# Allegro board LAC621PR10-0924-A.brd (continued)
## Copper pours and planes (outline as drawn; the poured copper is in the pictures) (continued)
INT_SPKR_L+ on BOTTOM (solid shape): 284.54,17.61 284.54,15.65 284.44,15.55 283.37,15.55 283.22,15.7 283.22,17.63 283.32,17.73 284.42,17.73
INT_SPKR_L- on BOTTOM (solid shape): 284.47,7.78 284.47,5.49 284.14,5.16 283.6,5.16 283.42,5.34 283.42,7.78 283.5,7.85 284.39,7.85
INT_SPKR_L- on BOTTOM (solid shape): 286.24,17.63 286.24,15.68 286.14,15.57 285.08,15.57 284.92,15.73 284.92,17.66 285.03,17.76 286.12,17.76
INT_SPKR_R+ on BOTTOM (solid shape): 288.02,17.61 288.02,15.65 287.92,15.55 286.85,15.55 286.7,15.7 286.7,17.63 286.8,17.73 287.9,17.73
INT_SPKR_R+ on BOTTOM (solid shape): 285.96,7.67 285.96,7.47 285.69,7.19 285.69,5.36 285.48,5.16 284.85,5.16 284.69,5.31 284.69,7.8 285.05,8.16 285.48,8.16
INT_SPKR_R- on BOTTOM (solid shape): 289.72,17.61 289.72,15.65 289.62,15.55 288.56,15.55 288.4,15.7 288.4,17.63 288.5,17.73 289.6,17.73
INT_SPKR_R- on BOTTOM (solid shape): 288.24,7.31 288.24,7.18 286.93,5.87 286.93,5.39 286.68,5.13 286.19,5.13 286.02,5.31 286.02,6.79 287.13,7.9 287.64,7.9
LX_1.8VALW on BOTTOM (solid shape): 214.5,109.7 215.3,109.7 215.59,109.41 215.59,107.48 215.09,106.99 210.98,106.99 210.68,107.29 210.68,108.26 210.78,108.36 212.84,108.36 213.17,108.69 213.17,109.48 213.4,109.71 214.49,109.71
LX_1V_PRIM on BOTTOM (solid shape): 201.87,69.45 201.87,68.25 202.14,67.97 203.64,67.97 204.41,67.21 204.94,67.21 205.07,67.09 205.07,66.37 204.96,66.27 201.18,66.27 201.08,66.37 201.08,69.47 201.15,69.55 201.76,69.55
LX_1VS_VCCIO on BOTTOM (solid shape): 202.45,53.45 202.45,52.73 202.35,52.63 201.26,52.63 201.13,52.51 201.13,51.08 200.95,50.91 199.44,50.91 198.84,50.31 198.37,50.31 198.23,50.45 198.23,53.14 198.63,53.55 202.35,53.55
LX_3V on TOP (solid shape): 219.67,73.36 219.67,72.75 219.54,72.62 219.26,72.62 218.71,72.06 217,72.06 216.75,71.81 216.75,71.45 216.6,71.3 215.02,71.3 214.92,71.4 214.92,73.26 215.1,73.44 219.59,73.44
LX_3V on BOTTOM (solid shape): 215.28,75 215.28,73.21 215.58,72.9 219.59,72.9 220.1,72.39 220.1,71.76 220.03,71.68 218.17,71.68 218.05,71.56 218.05,67.75 217.72,67.42 213.68,67.42 213.57,67.52 213.57,75.37 213.81,75.61 214.67,75.61
LX_5V on TOP (solid shape): 221.14,63.83 221.14,63.17 221.04,63.07 220.33,63.07 220.28,63.02 220.28,62.74 220.1,62.56 218.35,62.56 218.07,62.28 218.07,61.65 218.02,61.6 216.37,61.6 216.32,61.65 216.32,63.76 216.45,63.88 221.09,63.88
LX_5V on BOTTOM (solid shape): 219.56,63.95 221.49,63.95 221.63,63.81 221.63,63.28 221.86,63.05 221.86,62.49 221.75,62.39 220.34,62.39 218.99,61.04 218.99,58.8 218.83,58.65 216.55,58.65 216.47,58.73 216.47,63.61 216.83,63.96 219.54,63.96
NB_PSID on BOTTOM (solid shape): 53.79,94.02 53.79,94.01 53.85,93.92 53.93,93.85 53.94,93.83 53.95,93.8 53.95,93.14 52.73,91.93 45.7,91.93 45.63,91.99 45.63,92.74 45.67,92.78 52.17,92.78 53.48,94.09 53.71,94.09
PBAT_PRES#_C on BOTTOM (solid shape): 59.74,21.1 60.6,19.6 60.51,19.27 60.21,19.1 59.88,19.18 59.02,20.68 59.11,21.01 59.41,21.19
PBAT_SMBCLK_C on BOTTOM (solid shape): 62.33,22.6 63.19,21.1 63.11,20.77 62.8,20.6 62.48,20.68 61.62,22.18 61.71,22.51 62.01,22.69
PBAT_SMBDAT_C on BOTTOM (solid shape): 61.03,21.85 61.9,20.35 61.81,20.02 61.5,19.85 61.18,19.93 60.32,21.43 60.41,21.76 60.71,21.94
PBATT+_C on TOP (solid shape): 62.47,22.97 62.47,22.2 62.7,21.97 68.77,21.97 69.48,21.26 69.48,18.58 69.23,18.33 63.16,18.33 62.81,18.68 62.81,20.68 62.66,20.83 61.89,20.83 61.55,21.17 61.55,22.76 61.9,23.11 62.33,23.11
PBATT+_C on BOTTOM (solid shape): 66.18,25.35 66.2,25.35 66.22,25.33 67.8,23.09 68.11,22.79 68.11,18.73 67.73,18.35 64.07,18.35 63.98,18.45 63.97,18.46 63.97,18.48 63.97,19.52 63.5,19.99 63.5,21.81 63.38,21.93 62.76,22.84 62.76,23.33 64.79,25.35
RING2 on TOP (solid shape): 289.37,33.76 289.37,32.13 289.27,32.03 287.84,32.03 287.64,32.24 287.64,33.67 287.76,33.78 288.02,33.78 288.02,33.79 289.34,33.79
RING2 on TOP (solid shape): 283.91,32.44 283.91,32.41 283.93,32.39 283.93,32.34 284.11,32.16 284.11,32.01 283.97,31.87 283.79,31.87 283.52,32.14 283.51,32.14 283.38,32.26 283.2,32.26 283.09,32.38 281.76,32.38 281.7,32.44 281.7,32.57 281.72,32.59 283.76,32.59
RING2 on IN1 (solid shape): 288.78,33.02 288.78,31.78 288.25,31.25 283.98,31.25 283.12,32.11 283.12,32.44 283.25,32.57 286.73,32.57 287.49,33.33 288.48,33.33
RING2_R on TOP (solid shape): 295.06,34.36 295.06,31.83 294.85,31.63 293.92,31.63 293.56,31.98 293.56,33.53 293.43,33.66 293.36,33.66 293.25,33.56 293.25,32.31 292.98,32.03 289.75,32.03 289.62,32.16 289.62,32.85 289.72,32.95 291.68,32.95 291.98,33.25 291.98,34.07 292.47,34.55 294.87,34.55
RING2_R on IN2 (solid shape): 294.88,31.96 294.88,30.1 294.7,29.93 293.79,29.93 293.56,30.15 293.56,31.98 293.69,32.11 294.73,32.11
RING2_R on IN2 (solid shape): 301.48,19.43 301.79,19.43 302.17,19.05 302.17,18.6 301.93,18.36 300.47,18.36 299.78,19.05 299.78,19.26 299.6,19.43 299.38,19.43 299.22,19.59 299.22,20.76 299.27,20.81 300.11,20.81
SA_LGATE on BOTTOM (solid shape): 100.08,84.35 100.09,84.33 100.09,84.32 100.12,84.14 100.23,83.99 100.24,83.97 100.24,83.95 100.24,82.9 100.13,82.78 99.81,82.78 99.79,82.77 99.3,82.77 99.2,82.87 99.2,83.12 99.63,83.56 99.64,83.68 99.64,84.27 99.76,84.39 100.04,84.39
SA_LGATE on IN2 (solid shape): 100.09,84.22 100.1,84.2 100.13,84.1 100.2,84.01 100.21,83.99 100.22,83.97 100.22,83.82 100.52,83.52 100.52,82.81 100.44,82.73 99.44,82.73 99.07,83.1 99.07,84.19 99.2,84.32 99.99,84.32
SA_LGATE on IN2 (solid shape): 107.68,83.39 107.68,82.86 107.54,82.72 107.42,82.72 107.4,82.71 105.4,82.71 105.27,82.83 105.27,83.33 105.31,83.4 105.39,83.43 105.57,83.43 105.72,83.51 105.73,83.52 107.56,83.52
SA_SNUB on TOP (solid shape): 113.11,83.88 113.11,83.16 112.75,82.8 109.32,82.8 109.14,82.97 109.14,83.89 109.24,83.99 113,83.99
SA_SW on TOP (solid shape): 111.79,82.18 112.93,82.18 113.17,81.94 113.17,80.62 112.74,80.19 108.34,80.19 107.85,80.68 107.75,80.87 107.56,80.97 107.33,81.21 107.33,82.1 107.43,82.2 111.77,82.2
SA_SW on BOTTOM (solid shape): 110.43,83.9 110.43,80.83 110.15,80.55 108.19,80.55 107.68,81.06 107.33,81.06 106.69,81.69 102.53,81.69 102.07,82.15 102.07,82.3 101.7,82.67 101.7,82.69 101.68,82.69 101.56,82.81 101.43,82.81 101.38,82.86 101.38,83.49 101.5,83.6 102.03,83.6 102.19,83.45 102.2,83.45 102.27,83.38 103.02,83.38 103.62,82.78 107.61,82.78 107.89,83.07 107.89,83.71 108.22,84.03 110.29,84.03
SA_UGATE on BOTTOM (solid shape): 107.78,80.78 107.78,80.24 107.15,79.61 106.03,79.61 105.93,79.71 105.93,80.6 106.03,80.7 106.62,80.7 106.84,80.93 107.63,80.93
SA_UGATE on IN2 (solid shape): 103.08,81.41 103.08,80.47 102.98,80.37 101.48,80.37 101.33,80.52 101.33,81.41 101.41,81.49 103.01,81.49
SA_UGATE on IN2 (solid shape): 107.96,80.67 107.96,80.01 107.71,79.76 106.03,79.76 105.55,80.24 105.55,80.34 106.03,80.83 107.81,80.83
SLEEVE on TOP (solid shape): 290.77,41.13 290.77,40.91 289.88,40.03 289.88,39.79 289.59,39.5 289.29,39.5 289.17,39.63 289.17,41.02 289.44,41.3 290.59,41.3
SLEEVE on TOP (solid shape): 289.42,35.79 289.42,34.14 289.37,34.09 288.04,34.09 287.93,34.2 287.93,35.78 287.98,35.83 288.31,35.83 288.34,35.86 289.35,35.86
SLEEVE on TOP (solid shape): 283.91,33.13 283.91,32.77 283.86,32.72 283.49,32.72 283.35,32.75 283.21,32.72 281.7,32.72 281.7,32.97 281.72,33 282.91,33 283.08,33.17 283.16,33.15 283.25,33.15 283.32,33.15 283.39,33.16 283.49,33.2 283.83,33.2
SLEEVE on IN1 (solid shape): 290.56,40.49 290.56,38.87 290.41,38.71 290.26,38.71 289.57,38.03 289.55,38.03 289.25,37.92 289.14,37.62 289.14,37.6 288.91,37.37 288.91,34.27 288.4,33.76 286.5,33.76 285.51,32.77 282.94,32.77 282.84,32.87 282.84,33.07 282.97,33.2 283.11,33.2 283.12,33.2 283.3,33.15 283.49,33.2 283.68,33.2 285.23,34.75 286.98,34.75 287.31,35.08 287.31,37.89 287.34,37.91 287.46,38 287.54,38.13 287.55,38.14 288.02,38.61 288.04,38.61 288.27,38.72 288.38,38.95 288.38,38.97 289.06,39.65 289.06,40.54 289.24,40.72 290.33,40.72
SLEEVE_R on TOP (solid shape): 294.99,36.07 294.99,34.85 294.9,34.76 294.74,34.76 294.73,34.75 291.78,34.75 291.68,34.65 291.2,34.65 290.87,34.98 289.72,34.98 289.6,35.11 289.6,36.22 289.7,36.33 294.73,36.33
SLEEVE_R on TOP (solid shape): 295.13,30.96 295.13,29.66 293.08,27.62 292.23,27.62 291.97,27.36 291.97,25.99 292.91,25.05 292.91,24.36 292.97,24.3 292.97,21.16 293.41,20.73 297.93,20.73 299,19.66 299.5,19.66 299.79,19.37 299.79,18.47 299.65,18.34 298.26,18.34 296.94,19.65 291.81,19.65 291.5,19.96 291.5,24.02 290.51,25.02 290.51,28.78 291.27,29.54 292.98,29.54 293.37,29.94 293.37,30.33 293.28,30.42 292.62,30.42 292.44,30.6 292.44,31.38 292.5,31.44 292.51,31.44 292.52,31.45 294.64,31.45
SLEEVE_R on IN1 (solid shape): 294.83,35.03 294.83,34.34 294.33,33.84 294.33,33.83 293.36,32.86 293.36,30.74 293.03,30.41 292.24,30.41 292.01,30.64 292.01,33.55 293.12,34.66 293.14,34.66 293.74,35.26 294.6,35.26
SNB_+1VALWP on BOTTOM (solid shape): 221.93,56.14 221.93,55.12 221.93,55.12 221.93,54.16 221.86,54.09 219.95,54.09 219.77,54.27 219.77,56.16 219.78,56.17 219.78,56.39 219.86,56.47 221.6,56.47
SNUB_1.2V on BOTTOM (solid shape): 81.9,51.01 82.76,51.01 82.82,50.96 82.82,48.85 82.45,48.48 80.98,48.48 80.98,48.49 80.75,48.49 80.6,48.64 80.6,49.53 80.61,49.53 80.61,51.18 80.68,51.26 81.65,51.26
SNUB_1.8VALW on BOTTOM (solid shape): 212.84,110.33 212.84,108.67 212.69,108.51 210.98,108.51 210.86,108.64 210.86,109.48 210.97,109.59 210.97,110.28 211.12,110.43 212.74,110.43
SNUB_1V_PRIM on BOTTOM (solid shape): 205.09,69.32 205.09,67.82 204.99,67.72 204.15,67.72 203.92,67.95 203.92,69.27 204,69.35 205.07,69.35
SNUB_1VS_VCCIO on BOTTOM (solid shape): 200.09,50.27 200.28,50.22 200.47,50.27 201.05,50.27 201.1,50.22 201.1,49.54 200.98,49.42 200.6,49.42 200.49,49.43 200.39,49.42 199.44,49.42 199.27,49.58 199.27,50.19 199.35,50.27
SW_1.2V on BOTTOM (solid shape): 80.73,56.29 86.3,56.29 86.45,56.14 86.45,53.72 86.35,53.62 81.67,53.62 80.33,52.28 80.33,50.37 79.31,49.36 78.09,49.36 77.76,49.69 77.76,56.7 77.91,56.85 80.17,56.85
SW_1.2V on BOTTOM (solid shape): 91.38,53.57 91.38,53.34 91.36,53.33 91.36,53.18 90.84,52.66 90.54,52.66 90.36,52.48 88.53,52.48 88.4,52.61 88.4,53.5 88.45,53.55 89.06,53.55 89.14,53.47 90.29,53.47 90.38,53.47 90.54,53.62 91.32,53.62
SW_1.2V on IN1 (solid shape): 90.38,53.34 90.38,52.52 90.26,52.39 88.24,52.39 88.15,52.48 88.15,53.29 88.3,53.45 90.28,53.45
SW_1.2V on IN1 (solid shape): 81.41,55.6 81.41,55.25 81.51,55.15 82.27,55.15 82.35,55.07 82.35,54.23 82.17,54.06 80.8,54.06 80.64,54.21 80.64,55.55 80.77,55.68 81.33,55.68
SW_+1VALWP on TOP (solid shape): 224.37,54.06 224.37,52.77 224.35,52.75 224.35,52.24 224.17,52.06 222.22,52.06 221.93,52.35 221.93,53.8 222.23,54.11 224.32,54.11
SW_+1VALWP on BOTTOM (solid shape): 219.52,56.37 219.52,54.16 219.92,53.75 223.84,53.75 223.91,53.67 223.91,52.58 223.84,52.51 222.13,52.51 221.6,51.97 221.6,50.35 221.04,49.79 218.2,49.79 217.74,50.25 217.74,53.62 217.05,54.31 217.05,56.49 217.27,56.7 219.18,56.7
N15438178 on TOP (solid shape): 57.85,85.25 57.85,83.06 57.8,82.99 57.78,82.9 57.77,82.86 55.92,82.86 55.64,83.14 55.64,85.22 55.71,85.3 57.8,85.3
N15438178 on BOTTOM (solid shape): 56.6,85.75 56.6,84.23 57.03,83.8 57.7,83.8 57.8,83.7 57.8,83.02 57.77,82.99 57.77,82.78 57.72,82.73 56.3,82.73 55.79,83.24 55.79,83.62 55.26,84.15 54.37,84.15 54.19,84.33 54.19,86.01 54.29,86.11 56.25,86.11
N15443707 on BOTTOM (solid shape): 61.84,86.87 61.84,86.01 61.94,85.91 61.94,85.19 62.55,84.58 62.55,83.8 61.56,83.8 61.48,83.87 61.48,84.74 61.61,84.86 61.61,84.9 61.61,84.91 61.66,85.09 61.61,85.27 61.61,85.29 61.61,85.49 61.61,85.5 61.66,85.68 61.61,85.86 61.61,85.87 61.61,85.98 61.56,86.04 61.56,86.9 61.61,86.95 61.76,86.95
N17156948 on TOP (solid shape): 44.39,87.35 44.39,86.08 44.13,85.83 42.94,85.83 42.81,85.96 42.81,87.3 42.96,87.46 44.28,87.46
N19817114 on TOP (solid shape): 77.43,25.57 78.61,25.57 79.43,24.75 79.43,21.24 77.87,19.69 75.4,19.69 75.18,19.9 75.18,20.77 75.04,20.91 74.64,20.91 74.31,20.91 74.02,21.19 74.02,25.08 74.52,25.58 77.43,25.58
N19957038 on TOP (solid shape): 78.16,27.28 78.16,25.75 78.12,25.7 74.7,25.7 74.31,26.09 74.3,26.1 74.3,26.12 74.3,26.86 74.77,27.33 78.11,27.33
N32114561 on BOTTOM (solid shape): 62.57,83.11 62.57,82.4 62.52,82.35 60.39,82.35 60.34,82.4 60.34,83.14 60.36,83.16 62.52,83.16
N39307859 on BOTTOM (solid shape): 87.79,54.77 87.79,52.68 87.72,52.61 86.96,52.61 86.85,52.71 86.85,54.74 86.96,54.84 87.72,54.84
N39352217 on BOTTOM (solid shape): 220.08,71 220.08,70.34 219.92,70.18 219.92,67.9 219.87,67.85 218.96,67.85 218.86,67.95 218.86,69.68 219.16,69.98 219.16,71.02 219.21,71.07 220,71.07
N39352229 on BOTTOM (solid shape): 217.23,75.18 217.23,74.43 217.28,74.38 217.28,73.44 217.21,73.36 215.58,73.36 215.56,73.38 215.56,75.35 215.76,75.56 216.86,75.56
N39352417 on BOTTOM (solid shape): 221.83,61.73 221.83,61.07 221.55,60.79 221.55,60.53 220.81,59.8 220.81,58.58 220.69,58.45 219.92,58.45 219.75,58.63 219.75,59.97 220.89,61.12 220.89,61.68 220.99,61.78 221.78,61.78
N39352440 on BOTTOM (solid shape): 220.59,65.61 220.59,64.72 220.36,64.49 218.81,64.49 218.58,64.72 218.58,65.51 218.76,65.69 220.51,65.69
N39431059 on BOTTOM (solid shape): 92.37,68.46 92.37,66.27 92.34,66.25 91.68,66.25 91.58,66.35 91.58,68.46 91.63,68.51 92.32,68.51
N39431065 on BOTTOM (solid shape): 94.17,67.03 96.02,67.03 96.1,66.96 96.1,66.83 96.05,66.78 94.91,66.78 94.35,66.22 92.94,66.22 92.73,66.44 92.73,67.1 92.82,67.19 94.02,67.19
N39431067 on BOTTOM (solid shape): 94.71,68.62 94.71,67.97 95.12,67.56 95.14,67.53 95.17,67.51 95.24,67.44 96.02,67.44 96.1,67.36 96.1,67.21 96.05,67.16 94.27,67.16 93.97,67.47 93.04,67.47 92.93,67.58 92.93,68.6 93.03,68.7 94.63,68.7
N39431132 on BOTTOM (solid shape): 86.8,77.63 86.8,75.54 86.68,75.42 86.02,75.42 85.97,75.47 85.97,77.63 86.04,77.7 86.73,77.7
N39431138 on BOTTOM (solid shape): 88.25,76.2 89.78,76.2 89.85,76.13 89.85,75.92 88.86,75.92 88.85,75.92 88.82,75.92 88.32,75.42 87.39,75.42 87.39,76.31 87.46,76.38 88.07,76.38
N39431140 on BOTTOM (solid shape): 88.28,77.65 88.28,77.09 88.76,76.61 89.78,76.61 89.85,76.53 89.85,76.36 89.83,76.33 88.53,76.33 88.52,76.34 88.34,76.34 88.02,76.66 87.46,76.66 87.39,76.74 87.39,77.68 87.44,77.73 88.2,77.73
N39435438 on BOTTOM (solid shape): 101.21,81.36 101.21,80.39 101.43,80.17 101.81,80.17 101.89,80.09 101.89,79.07 101.79,78.97 101.21,78.97 100.88,79.3 100.88,81.36 100.93,81.41 101.15,81.41
N39435440 on BOTTOM (solid shape): 103.39,81.06 103.39,79.12 103.26,79 102.6,79 102.48,79.12 102.48,80.27 102.37,80.37 102.37,80.51 102.38,80.52 102.41,80.67 102.38,80.83 102.37,80.84 102.37,81.09 102.39,81.13 103.31,81.13
N49522780 on TOP (solid shape): 39.97,82.43 39.97,81.72 40.14,81.54 41.28,81.54 41.47,81.35 41.47,80.86 41.23,80.62 39.13,80.62 39.03,80.73 39.03,81.79 39.25,82.02 39.25,82.48 39.31,82.53 39.86,82.53

Small or netless copper shapes (teardrops, artwork), in the pictures only: 175 on TOP, 66 on BOTTOM, 79 on IN2, 30 on IN3

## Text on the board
Ref Des/Silkscreen Bottom: H23 | H8 | H7 | PWB:6N3K7 | COPYRIGHT 2015 | REV:A00 | ALL RIGHT RESERVED
User.Comments: LA-C621P | 2016-09-24 | 2015-09-24 | ADM60 | Win | 275.67 | 223.15 | 209.00 | 56.09 | 19.37 | 0.41 | 8.41 | 13.50 | 101.80 | 61.24 | 3.44 | 0.00 | 28.40 | 95.72 | 35.55 | 39.75 | 21.20 | 51.63 | 95.48 | 81.10 | 81.00 | 66.95 | 19.31 | 14.60 | 239.73 | 225.27 | 193.85 | 156.60 | 0.54 | 57.21 | 16.78 | 0.43 | 83.30 | 94.42 | 37.15 | 98.42 | 3.35 | 211.49 | 86.30 | 76.45 | 44.30 | 31.15 | 12.45 | 2.40 | 225.25 | 212.23 | 130.23 | 47.40 | 24.55 | 20.60 | 16.81 | 8.40 | 80.73 | 72.20 | 35.71 | 12.20 | 9.48 | 3.86 | 0.65 | PCB CONNECTOR_TOP | PCB LIMIT_TOP | PCB LIMIT_BTM | PCB CONNECTOR_BTM
USER_PART_NUM_BOTTOM: 275.67 | 223.15 | 209.00 | 56.09 | 19.67 | 0.41 | 8.41 | 13.50 | 101.80 | 61.24 | 3.44 | 0.00 | 28.40 | 95.72 | 34.95 | 39.75 | 20.60 | 51.63 | 83.30 | 94.42 | 37.15 | 98.35 | 3.35 | 211.49 | 86.30 | 76.45 | 44.30 | 31.15 | 12.45 | 2.40
DEVICE_TYPE_BOTTOM: 95.48 | 81.10 | 81.00 | 66.95 | 19.31 | 14.60 | 239.73 | 225.27 | 193.85 | 156.60 | 0.54 | 57.21 | 16.58 | 0.53 | 225.25 | 212.23 | 130.23 | 61.30 | 47.40 | 24.55 | 20.60 | 16.81 | 8.40 | 0.00 | 80.73 | 72.20 | 35.71 | 12.20 | 9.48 | 3.86 | 0.65 | 57.01
DEVICE_TYPE_TOP: {\Fgdt;n}\Fcgomg.ttf;6.50 | {\Fgdt;n}\Fcgomg.ttf;8.00 | {\Fgdt;n}\Fcgomg.ttf;3.80 | {\Fgdt;n}\Fcgomg.ttf;2.40 | 281.10 | 3.00 | 2.00 | 238.85 | 187.10 | {\Fgdt;n}\Ftxt;3.30 | 170.85 | 104.85 | 67.85 | 38.15 | 37.35 | 11.68 | 5.85 | 103.60 | 80.35 | 49.00 | 48.50 | 6.50 | 0.00 | 43.00 | 62.95 | 101.00 | 92.50 | 83.05 | 74.15 | 46.85 | 14.00 | 6.70 | 6.05 | 245.60 | 168.20 | 137.85 | 107.50 | 59.85 | 52.75 | {\Fgdt;n}\Ftxt;3.20 | 4.15
PAGE_OUTLINE: 101.40 | 101.00 | 92.50 | 83.05 | 74.15 | 46.85 | 6.70 | {\Fgdt;n}\Ftxt;2.40 | {\Fgdt;n}\Ftxt;6.50 | 238.85 | {\Fgdt;n}\Ftxt;3.30 | 187.10 | {\Fgdt;n}\Ftxt;8.00 | {\Fgdt;n}\Ftxt;5.50 | {\Fgdt;n}\Ftxt;3.80 | 170.85 | 153.85 | 104.85 | 67.85 | {\Fgdt;n}\Ftxt;3.20 | 37.35 | 11.68 | 5.85 | 281.10 | 245.60 | 168.20 | 137.85 | 107.50 | 59.85 | 52.75 | 38.15 | 0.00 | 4.15 | 103.60 | 100.00 | 80.35 | 62.95 | 49.00 | 48.50 | 43.00 | 6.50 | 2.00
User.11: 107.75 | 0.00 | 5.35 | 291.10 | 15.20
User.12: 275.67 | 223.15 | 209.00 | 56.09 | 19.67 | 0.41 | 8.41 | 13.50 | 101.80 | 61.24 | 3.44 | 0.00 | 28.40 | 95.72 | 34.95 | 39.75 | 20.60 | 51.63 | 83.30 | 94.42 | 37.15 | 98.35 | 3.35 | 211.49 | 86.30 | 76.45 | 44.30 | 31.15 | 12.45 | 2.40
User.13: 95.48 | 81.10 | 81.00 | 66.95 | 19.31 | 14.60 | 239.73 | 225.27 | 193.85 | 156.60 | 0.54 | 57.21 | 16.58 | 0.53 | 225.25 | 212.23 | 130.23 | 61.30 | 47.40 | 24.55 | 20.60 | 16.81 | 8.40 | 0.00 | 80.73 | 72.20 | 35.71 | 12.20 | 9.48 | 3.86 | 0.65 | 57.01
User.16: {\Fgdt;n}\Fcgomg.ttf;6.50 | {\Fgdt;n}\Fcgomg.ttf;8.00 | {\Fgdt;n}\Fcgomg.ttf;3.80 | {\Fgdt;n}\Fcgomg.ttf;2.40 | 281.10 | 3.00 | 2.00 | 238.85 | 187.10 | {\Fgdt;n}\Ftxt;3.30 | 170.85 | 104.85 | 67.85 | 38.15 | 37.35 | 11.68 | 5.85 | 80.35 | 49.00 | 48.50 | 6.50 | 0.00 | 43.00 | 101.00 | 92.50 | 83.05 | 74.15 | 46.85 | 14.00 | 6.70 | 6.05 | 245.60 | 168.20 | 137.85 | 107.50 | 59.85 | 52.75 | {\Fgdt;n}\Ftxt;3.20 | 4.15 | PCB PAD_TOP
User.17: 101.40 | 101.00 | 92.50 | 83.05 | 74.15 | 46.85 | 6.70 | {\Fgdt;n}\Ftxt;2.40 | {\Fgdt;n}\Ftxt;6.50 | 238.85 | {\Fgdt;n}\Ftxt;3.30 | 187.10 | {\Fgdt;n}\Ftxt;8.00 | {\Fgdt;n}\Ftxt;5.50 | {\Fgdt;n}\Ftxt;3.80 | 170.85 | 153.85 | 104.85 | 67.85 | {\Fgdt;n}\Ftxt;3.20 | 37.35 | 11.68 | 5.85 | 281.10 | 245.60 | 168.20 | 137.85 | 107.50 | 59.85 | 52.75 | 38.15 | 0.00 | 4.15 | 103.60 | 100.00 | 80.35 | 62.95 | 49.00 | 48.50 | 43.00 | 6.50 | 2.00
User.19: 107.75 | 0.00 | 5.35 | 291.10 | 15.20
User.32: SOLDERMASK_TOP
User.33: SOLDERMASK_BOTTOM
User.42: 6.6mil | 5.7mil | 4.8mil | 3.5mil | 4mil | 4mil/3.7mil | 3.7mil/3.9mil | 4.4mil/5.3mil | 4.8mil/4.3mil | Width/Space | 3.7mil/11.3mil | 3.2mil/6.7mil | SB_1_2MM-10L(4MIL 50ohm)_WithOutC_131024 | 85ohm
User.43: FIGURE | SIZE | 8.0 | 20.0 | 28.0 | 35.0 | 39.0 | 55.0 | 94.0 | 126.0 | 130.0 | 150.0 | 31.0 | 40.0 | 43.0 | 63.0 | 102.0 | 39.0x33.0 | 45.0x37.0 | 55.0x24.0 | 67.0x31.0 | 69.0x39.0 | 71.0x31.0 | 75.0x31.0 | 75.0x37.0 | 79.0x31.0 | 94.0x28.0 | 100.0x31.0 | 102.0x31.0 | 112.0x39.0 | 118.0x33.0 | 67.0x43.0 | 118.0x79.0 | DRILL CHART: TOP to BOTTOM | ALL UNITS ARE IN MILS | TOLERANCE | +3.0/-3.0 | +2.0/-2.0 | PLATED | NON-PLATED | QTY | 6025 | 19 | 42 | 10 | 7 | 2 | 13 | 1 | 5 | 4 | 3 | 6
